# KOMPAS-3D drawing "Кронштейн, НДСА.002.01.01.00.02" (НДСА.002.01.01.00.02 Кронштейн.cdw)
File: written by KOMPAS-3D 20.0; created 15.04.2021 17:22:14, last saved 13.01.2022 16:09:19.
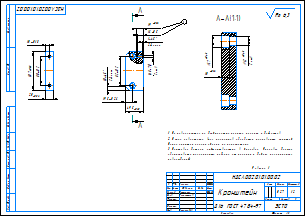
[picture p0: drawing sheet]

Sheet 1: A3, landscape

Document properties: Автор: 111; Параметр неуказанной шероховатости: Ra 6,3; PLM_CDWXDTO: <item xmlns="http://appius.ru/pdm" xmlns:xs="http://www.w3.org/2001/XMLSchema" xmlns:xsi="http://www.w3.org/2001/XMLSchema-instance" xsi:type="item">  <element xmlns:d2p1="http://v8.1c.ru/8.1/data/enterprise/current-config" xsi:type="d2p1:CatalogRef.aps_Элемен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; Полное имя файла: НДСА.002.01.01.00.02 Кронштейн.m3d; Масса: 0.268074; PDM_DOCXDTO: <item xmlns="http://appius.ru/pdm" xmlns:xs="http://www.w3.org/2001/XMLSchema" xmlns:xsi="http://www.w3.org/2001/XMLSchema-instance" xsi:type="item">  <element xmlns:d2p1="http://v8.1c.ru/8.1/data/enterprise/current-config" xsi:type="d2p1:CatalogRef.aps_Элемен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; PDM_ITEMXDTO: <item xmlns="http://appius.ru/pdm" xmlns:xs="http://www.w3.org/2001/XMLSchema" xmlns:xsi="http://www.w3.org/2001/XMLSchema-instance" xsi:type="item">  <element xmlns:d2p1="http://v8.1c.ru/8.1/data/enterprise/current-config" xsi:type="d2p1:CatalogRef.aps_Элемен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; PDM_DRAWINGXDTO: <item xmlns="http://appius.ru/pdm" xmlns:xs="http://www.w3.org/2001/XMLSchema" xmlns:xsi="http://www.w3.org/2001/XMLSchema-instance" xsi:type="item">  <element xmlns:d2p1="http://v8.1c.ru/8.1/data/enterprise/current-config" xsi:type="d2p1:CatalogRef.aps_Элемен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

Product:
- Part/product: Кронштейн  | designation НДСА.002.01.01.00.02
    Материал: Д16  ГОСТ 4784-97 (density 2800 kg/m3)
    Масса: 0.268074
    additional columns: <item xmlns="http://appius.ru/pdm" xmlns:xs="http://www.w3.org/2001/XMLSchema" x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; <item xmlns="http://appius.ru/pdm" xmlns:xs="http://www.w3.org/2001/XMLSchema" x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; <item xmlns="http://appius.ru/pdm" xmlns:xs="http://www.w3.org/2001/XMLSchema" x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
    source file: НДСА.002.01.01.00.02 Кронштейн.cdw

Title block, sheet 1: Наименование: Кронштейн; designation: НДСА.002.01.01.00.02; Материал: Д16  ГОСТ 4784-97; Масса: 0,27; Количество листов документа: 1; organisation: ЭСТО; Форматы листов документа: A3; stored path: C:\Users\s.pischagina\Desktop\PLM\НДСА.002.01.01.00.02 Кронштейн.cdw; Разработал: Пищагина; Проверил: Горностаев; Утвердил: Виноградов; Разработал, date: 15.04.21

Views: Вид 1, Снизу, Проекционный вид 2, Местный разрез 1, Разрез А-А
Referenced files in C:\Users\s.pischagina\Desktop\PLM\: НДСА.002.01.01.00.02 Кронштейн.m3d
Referenced files in C:\Users\korychko\Desktop\PLM\: НДСА.002.01.01.00.02 Кронштейн.m3d
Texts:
  Ревизия 1
  Ra 6,3
  Корячко
  НДСА.002.01.01.00.02 Кронштейн
Dimensions and other numbers on the sheet: 80±0,2; 107; 10±0,18; 20; 82±0,2; 19,5±0,26; 2фаски; 49,5; 1; 16; 19; -7Н; 8; 2отв; 12; 17; 3; 1:2; 0,27; 15.04.21; 774; 13.01.2022

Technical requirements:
  На поверхностях не допускается наличие царапин и дефектов.
  После завершения всех процессов обработки произвести очистку.
  После очистки голыми руками не прикасаться.
  Поставка детали осуществляется в упаковке. Упаковка должна
  обеспечивать сохранность изделия от царапин и других механических
  повреждений.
